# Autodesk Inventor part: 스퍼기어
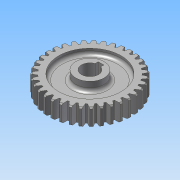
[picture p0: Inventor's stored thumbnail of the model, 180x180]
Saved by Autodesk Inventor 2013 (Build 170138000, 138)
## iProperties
Created: 2013-08
Part Number: 스퍼기어
Material: 강
Document SubType Name: Modeling
Designer: 한국산업디자인학원
Categories: <?xml version="1.0" encoding="UTF-16"?> <MemberInstance><Categories><FamilyTemplate><FamilyTemplateParameter ValueType="xs:double" Id="1" ObjectReferenceKey="da
Density: 1 g/cm^3
CustomPartVersion: 1
Author: 한국산업디자인학원
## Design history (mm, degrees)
sketch "Sketch1"
  geometry: C1 r 37 at (0, 0)
  constraints: 1 centre point
  dimensions: "d0" = 74 diameter of C1 (= da_da)
extrude "Extrusion1" new body sketch "Sketch1" distance "d1" = 15 (= da_b); taper "d2" = 0 deg
chamfer "모따기1" distance "d49" = 1; stored, may be unused: second distance "d50" = 2, angle "d51" = 45 deg
workplane "Work Plane2"
feature "피치 지름" dims "d4" = 10, "d5" = 0
workplane "Work Plane8"
workplane "Work Plane9"
feature "스퍼 기어" dims "da_b" = 15, "da_d" = 70, "da_aw" = 70, "da_da" = 74, "da_df" = 65, "da_dw" = 70, angle "da_beta" = 0 deg, "da_lefttooth" = 0, "da_righttooth" = 0
sketch "스케치3"
  geometry: C1 r 12.5 at (0, 0); C2 r 27.5 at (0, 0); A1 r 36 centre (0, 0) between (-5.215, 35.62) and (-7.633, 35.181) reference
  constraints: 2 centre point, 2 coincident
  dimensions: "d52" = 25 diameter of C1; "d54" = 55 diameter of C2
extrude "돌출2" cut sketch "스케치3" distance "d55" = 5; taper "d56" = 0 deg
node "작업 평면11"
fillet "모깎기1" dims "d57" = 3
extrude "돌출3" join sketch "스케치3" distance "d58" = 3; taper "d60" = 0 deg; dims "d59" = 28, "d61" = 0
sketch "스케치4"
  geometry: L1 (-2.5, 7.071)-(-2.5, 9.8); L2 (-2.5, 9.8)-(2.5, 9.8); L3 (2.5, 9.8)-(2.5, 7.071); C1 r 12.5 at (0, 0) reference; A1 r 7.5 centre (0, 0) between (-2.5, 7.071) and (2.5, 7.071); 1 further point
  constraints: 6 end point, 2 point on circle, 1 centre point, 1 coincident, 1 midpoint, 1 parallel, 1 perpendicular, 1 vertical, 1 vertical alignment
  dimensions: "d62" = 15 diameter of A1; "d64" = 5 distance of L1.end L2.end; "d65" = 17.3 dimension on A1 L2
extrude "돌출4" cut sketch "스케치4" stored distance "d66" = 3; taper "d67" = 0 deg
body "Solid1"
mirror "대칭1"
sketch "Sketch2"
  geometry: C1 r 37 at (0, 0) reference; C2 r 35 at (0, 0)
  constraints: 1 centre point, 1 coincident
  dimensions: "d3" = 70 diameter of C2 (= da_dw)
body "Srf1"
other parameters: "d17" = 0, "d34" = 0.8976 (computed from da_z), "d39" = 0, "d41" = 0, "d47" = 0, "d48" = 0
